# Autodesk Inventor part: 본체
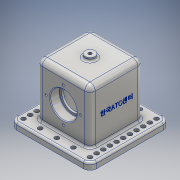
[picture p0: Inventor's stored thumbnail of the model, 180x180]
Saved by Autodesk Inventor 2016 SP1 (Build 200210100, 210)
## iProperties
Created: 2018-11
Part Number: 본체
Material: 알루미늄 6061
Document SubType Name: Modeling
Designer: basic
Density: 2.7 g/cm^3
Appearance: 알루미늄 - 평지
Mass: 1016.99 g
Surface Area: 777.082 cm^2
Volume: 376.663 cm^3
Author: basic
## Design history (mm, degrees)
sketch "스케치1"
  geometry: L1 (-60, -60)-(60, -60); L2 (60, -60)-(60, 60); L3 (60, 60)-(-60, 60); L4 (-60, 60)-(-60, -60); L5 (-60, -60)-(60, 60); L6 (60, -60)-(-60, 60); 1 further point
  constraints: 12 end point, 2 midpoint, 2 parallel, 2 perpendicular, 1 horizontal
  dimensions: "d0" = 120 distance of L2.end L3.end
extrude "돌출1" new body sketch "스케치1" distance "d1" = 10; taper "d2" = 0 deg
sketch "스케치2"
  geometry: L1 (-40, -40)-(40, -40); L2 (40, -40)-(40, 40); L3 (40, 40)-(-40, 40); L4 (-40, 40)-(-40, -40); L5 (-40, -40)-(40, 40); L6 (40, -40)-(-40, 40); 1 further point
  constraints: 12 end point, 2 midpoint, 2 parallel, 2 perpendicular, 1 horizontal
  dimensions: "d3" = 80 distance of L2.end L3.end
extrude "돌출2" join sketch "스케치2" distance "d4" = 80; taper "d5" = 0 deg
sketch "스케치3"
  geometry: L1 (40, -10)-(40, 38); C1 r 20 at (40, 38)
  constraints: 2 end point, 1 centre point, 1 coincident, 1 vertical
  dimensions: "d6" = 48 distance of L1.start L1.end; "d7" = 40 diameter of C1
extrude "돌출3" cut sketch "스케치3" distance "d8" = 14; taper "d9" = 0 deg
sketch "스케치4"
  geometry: C1 r 20 at (0, 0) reference; C2 r 16.5 at (0, 0); 1 further point
  constraints: 1 centre point, 1 coincident
  dimensions: "d11" = 33 diameter of C2
extrude "돌출4" cut sketch "스케치4" distance "d12" = 3; taper "d13" = 0 deg
sketch "스케치5"
  geometry: L1 (30, -23)-(-30, -23); L2 (-30, -23)-(-30, 23); L3 (-30, 23)-(30, 23); L4 (30, 23)-(30, -23); L5 (30, -23)-(-30, 23); L6 (-30, -23)-(30, 23); 1 further point
  constraints: 12 end point, 2 midpoint, 2 parallel, 1 horizontal, 1 perpendicular
  dimensions: "d14" = 60 distance of L2.end L3.end; "d15" = 46 distance of L1.end L2.end
extrude "돌출5" cut sketch "스케치5" distance "d16" = 80; taper "d17" = 0 deg
sketch "스케치6"
  geometry: L1 (40, 38)-(40, 64); C1 r 20 at (40, 38) reference; 2 further points
  constraints: 2 end point, 1 coincident, 1 vertical
  dimensions: "d19" = 26 distance of L1.start L1.end
hole "구멍1" sketch "스케치6" at (40, 64) diameter "d20" = 3.242; stored, may be unused: countersink angle "d24" = 90 deg, drill point angle "d26" = 118 deg; dims "d21" = 8, "d22" = 4, "d23" = 2, "d25" = 10
node "작업 평면1"
sketch "스케치7"
  geometry: C1 r 7.5 at (0, 0); 1 further point
  constraints: 1 centre point, 1 coincident
  dimensions: "d31" = 15 diameter of C1
extrude "돌출6" join sketch "스케치7" stored distance "d32" = 80; taper "d33" = 0 deg
sketch "스케치8"
  geometry: 2 further points
  constraints: 1 coincident
hole "구멍2" sketch "스케치8" at (0, 0) diameter "d34" = 4.917; stored, may be unused: countersink angle "d38" = 90 deg, drill point angle "d40" = 118 deg; dims "d35" = 12, "d36" = 4, "d37" = 2, "d39" = 17.1
fillet "모깎기1" dims "d41" = 10
sketch "스케치9"
  geometry: A1 r 10 centre (-50, -50) between (-60, -50) and (-50, -60) reference; 2 further points
  constraints: 1 coincident
hole "구멍3" sketch "스케치9" at (-50, -50) diameter "d42" = 6.6; stored, may be unused: countersink angle "d46" = 90 deg, drill point angle "d48" = 118 deg; dims "d43" = 12, "d44" = 4, "d45" = 2, "d47" = 17.1
fillet "모깎기2" dims "d68" = 8
fillet "모깎기3" dims "d69" = 8
fillet "모깎기4" dims "d70" = 3
fillet "모깎기5" dims "d71" = 3
fillet "모깎기6" dims "d72" = 3
fillet "모깎기7" dims "d73" = 0.6
chamfer "모따기1" distance "d74" = 1; stored, may be unused: second distance "d75" = 2, angle "d76" = 45 deg
fillet "모깎기8" dims "d77" = 3
fillet "모깎기9" dims "d78" = 3
sketch "스케치11"
  geometry: L1 (82, -18)-(82, 82) reference; 3 further points
  constraints: 1 horizontal alignment, 1 midpoint, 1 other
  dimensions: "d79" = 48 distance from line of L1 point (34, 32)
feature "엠보싱1" sketch "스케치11" dims "d0" = 120, "d80" = 0.5, "d81" = 0
node "솔리드1"
pattern_circular "원형 패턴1" dims angle "d28" = 360 deg
mirror "대칭1"
pattern_linear "직사각형 패턴1" dims "d51" = 25
pattern_linear "직사각형 패턴2"
mirror "대칭2"
mirror "대칭3"
other parameters: "d30" = 95
